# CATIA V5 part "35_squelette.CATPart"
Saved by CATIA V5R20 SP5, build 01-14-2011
Part number: 35_squelette
Publications: "Plan yz", "Droite.1", "Point.2"
Bounding box of the stored display mesh (mm): x 0 to 0, y 33.362 to 39.362, z -252.294 to 9.706
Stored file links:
  C:\Documents and Settings\anizard\Bureau\13\35_squelette.CATPart
  C:\Documents and Settings\anizard\Bureau\13\anizard.CATProduct
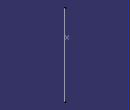
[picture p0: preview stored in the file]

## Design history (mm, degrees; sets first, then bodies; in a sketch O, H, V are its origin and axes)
Set1
  Line1: linked copy from another document
  Point1: linked copy from another document
  Plane1: linked copy from another document
  Point2: linked copy from another document
  Plane2: linked copy from another document
  Plane3: linked copy from another document
Body1 (main body)
  Line2: type PtDir, RefPoint Point2, Direction Plane3, Start -80, End 182
  Point3: (0, 6, 0), relative to Point2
